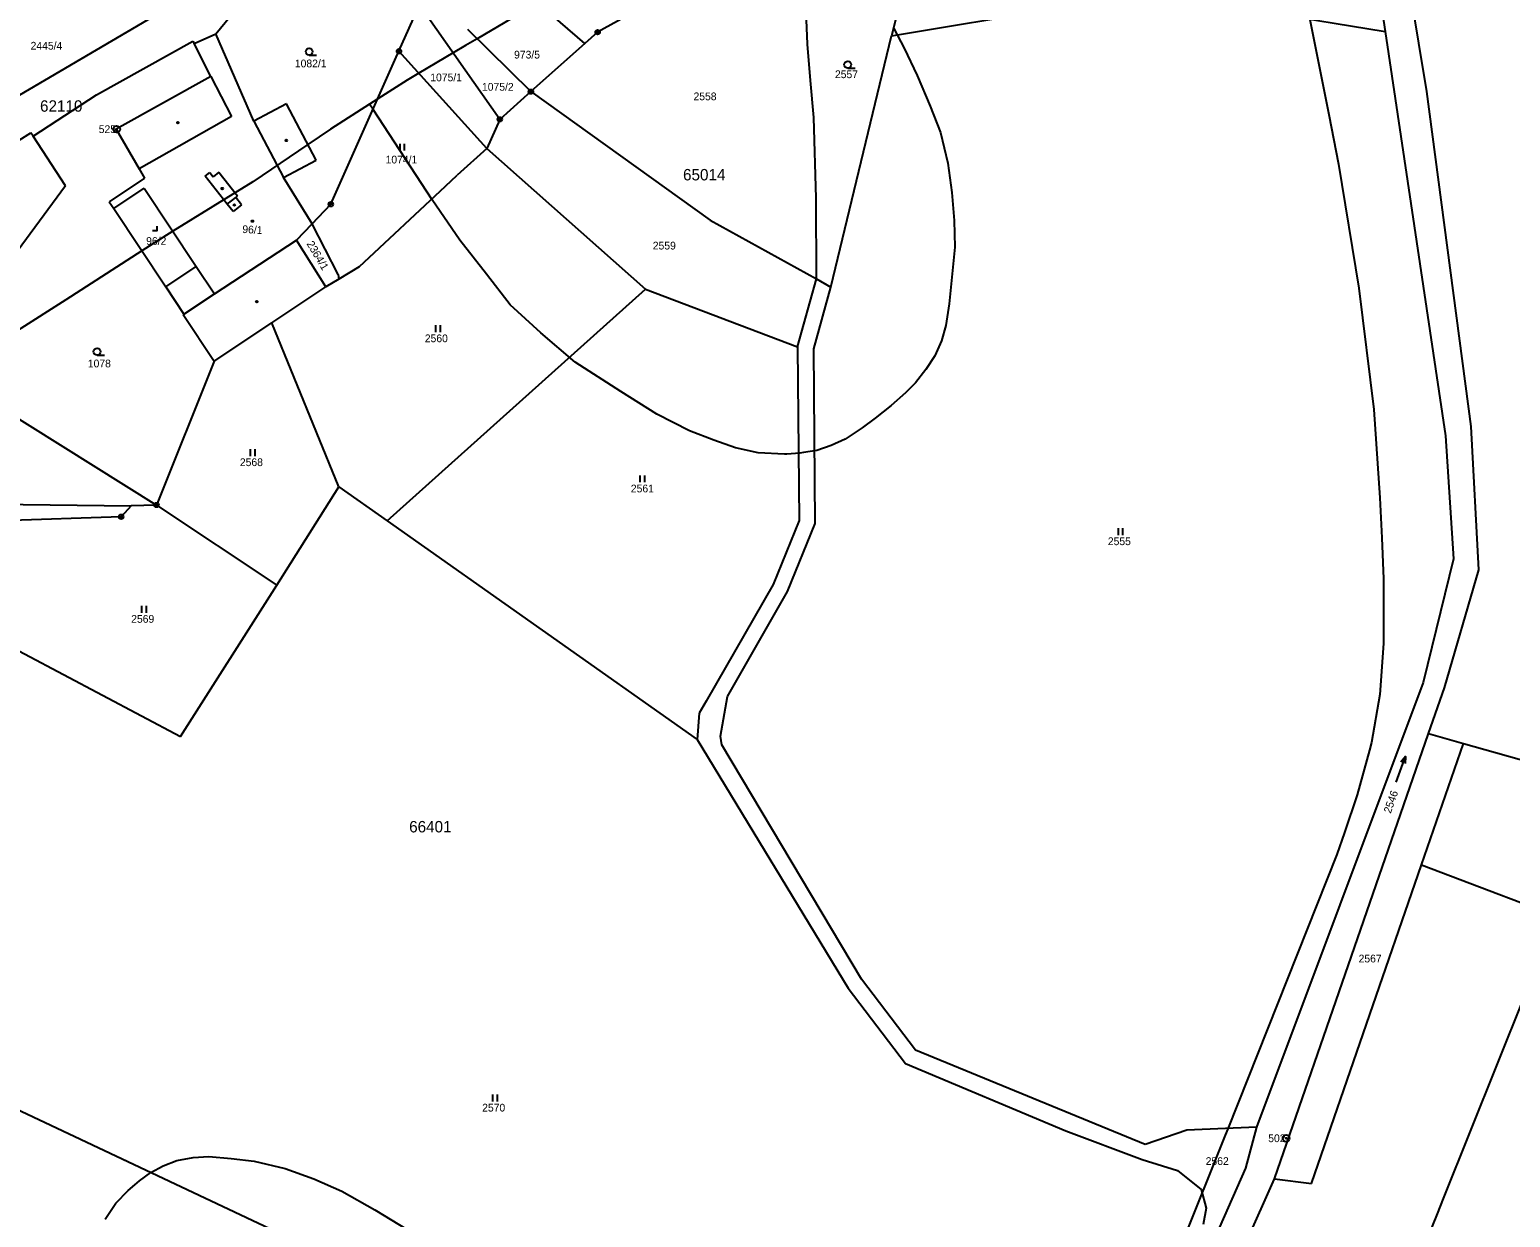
# Model space of a CAD drawing. Extents: x -546762 to -540209, y -1046851 to -1035694.
# Drawn here: x -543169.9 to -542845.1, y -1040575.9 to -1040315.5 of the extents above; entities that cross this region are included whole.
import ezdxf

# ---------------------------------------------------------------- set-up
doc = ezdxf.new("R2010")
doc.units = 0
for name, color, linetype in [('Vrstva 1', 7, 'Continuous'), ('Vrstva 17', 7, 'Continuous'), ('Vrstva 18', 7, 'Continuous'), ('Vrstva 19', 7, 'Continuous'), ('Vrstva 24', 7, 'Continuous'), ('Vrstva 25', 7, 'Continuous'), ('Vrstva 3', 7, 'Continuous'), ('Vrstva 37', 7, 'Continuous'), ('Vrstva 4', 7, 'Continuous'), ('Vrstva 52', 7, 'Continuous'), ('Vrstva 53', 7, 'Continuous')]:
    doc.layers.add(name, color=color, linetype=linetype)

msp = doc.modelspace()

# ---------------------------------------------------------------- linework, layer by layer
at = {"layer": 'Vrstva 1'}
msp.add_line((-543102.19, -1040369.21), (-543102.05, -1040370.19), dxfattribs=at)
for points in [[(-542876.59, -1040289.15), (-542872.58, -1040315.87)], [(-542974.46, -1040291.54), (-542980.8, -1040316.89)], [(-543188, -1040339.15), (-543119.06, -1040298.69)], [(-542999.24, -1040318.65), (-543000.14, -1040297.52)], [(-542863.38, -1040329.08), (-542868.75, -1040296.78)], [(-543023.91, -1040304.21), (-543045.27, -1040316.06)], [(-543048.07, -1040318.56), (-543058.79, -1040309.3)], [(-543129.03, -1040316.45), (-543125.93, -1040312.7)], [(-543088.85, -1040320.24), (-543084.34, -1040310.1)], [(-543066.73, -1040335.17), (-543084.34, -1040310.1)], [(-542980.8, -1040316.89), (-542944.78, -1040310.88)], [(-542898.51, -1040311.7), (-542872.58, -1040315.87)], [(-543073.81, -1040315.43), (-543059.9, -1040329.09)], [(-542872.58, -1040315.87), (-542859.29, -1040404.58)], [(-543155.2, -1040329.77), (-543134.03, -1040318)], [(-543134.03, -1040318), (-543133.76, -1040318.53)], [(-543133.76, -1040318.53), (-543129.03, -1040316.45)], [(-543130.09, -1040325.75), (-543133.76, -1040318.53)], [(-543120.69, -1040335.53), (-543129.03, -1040316.45)], [(-543048.07, -1040318.56), (-543059.9, -1040329.09)], [(-543045.27, -1040316.06), (-543048.07, -1040318.56)], [(-542998.62, -1040326.65), (-542999.24, -1040318.65)], [(-542994.15, -1040371.97), (-542980.8, -1040316.89)], [(-543103.78, -1040353.78), (-543088.85, -1040320.24)], [(-543069.55, -1040341.59), (-543088.85, -1040320.24)], [(-543130.09, -1040325.75), (-543150.86, -1040337.29)], [(-542997.83, -1040334.73), (-542998.62, -1040326.65)], [(-543169.09, -1040338.87), (-543155.2, -1040329.77)], [(-543113.53, -1040331.74), (-543120.69, -1040335.53)], [(-543106.98, -1040344.11), (-543113.53, -1040331.74)], [(-543059.9, -1040329.09), (-543066.73, -1040335.17)], [(-543059.9, -1040329.09), (-543020.6, -1040357.3)], [(-542853.67, -1040402.48), (-542863.38, -1040329.08)], [(-543066.73, -1040335.17), (-543069.55, -1040341.59)], [(-542997.35, -1040352.46), (-542997.83, -1040334.73)], [(-543192.68, -1040352.56), (-543169.57, -1040338.13)], [(-543169.09, -1040338.87), (-543169.57, -1040338.13)], [(-543150.86, -1040337.29), (-543145.83, -1040346)], [(-543161.98, -1040349.72), (-543169.09, -1040338.87)], [(-543069.55, -1040341.59), (-543076.05, -1040347.39)], [(-543069.55, -1040341.59), (-543034.74, -1040372.42)], [(-543114.14, -1040347.9), (-543106.98, -1040344.11)], [(-543144.63, -1040348.09), (-543152.39, -1040353.25)], [(-543145.83, -1040346), (-543144.63, -1040348.09)], [(-543107.86, -1040358.04), (-543114.14, -1040347.9)], [(-543078.67, -1040349.8), (-543076.05, -1040347.39)], [(-543161.98, -1040349.72), (-543174.41, -1040366.6)], [(-543151.42, -1040354.71), (-543144.73, -1040350.26)], [(-543144.73, -1040350.26), (-543133.29, -1040367.45)], [(-543097.58, -1040367.53), (-543078.67, -1040349.8)], [(-543152.39, -1040353.25), (-543151.42, -1040354.71)], [(-543151.42, -1040354.71), (-543139.98, -1040371.9)], [(-543107.86, -1040358.04), (-543103.78, -1040353.78)], [(-542997.29, -1040370.12), (-542997.35, -1040352.46)], [(-543111.3, -1040361.62), (-543107.86, -1040358.04)], [(-543102.19, -1040369.21), (-543107.86, -1040358.04)], [(-543020.6, -1040357.3), (-542997.29, -1040370.12)], [(-543104.91, -1040371.89), (-543111.3, -1040361.62)], [(-543133.29, -1040367.45), (-543129.3, -1040373.44)], [(-543097.58, -1040367.53), (-543102.05, -1040370.19)], [(-543102.05, -1040370.19), (-543104.91, -1040371.89)], [(-543001.4, -1040385.03), (-542997.29, -1040370.12)], [(-542997.29, -1040370.12), (-542994.15, -1040371.97)], [(-543139.98, -1040371.9), (-543136.02, -1040377.85)], [(-543136.02, -1040377.85), (-543129.3, -1040373.44)], [(-543116.72, -1040379.75), (-543104.91, -1040371.89)], [(-543091.43, -1040423.21), (-543034.74, -1040372.42)], [(-543034.74, -1040372.42), (-543001.4, -1040385.03)], [(-542997.88, -1040385.49), (-542994.15, -1040371.97)], [(-543136.02, -1040377.85), (-543136.19, -1040377.96)], [(-543136.19, -1040377.96), (-543129.37, -1040388.16)], [(-543129.37, -1040388.16), (-543116.72, -1040379.75)], [(-543102.01, -1040415.76), (-543116.72, -1040379.75)], [(-543001.4, -1040385.03), (-543001.07, -1040423.13)], [(-542997.54, -1040423.8), (-542997.88, -1040385.49)], [(-543191.01, -1040389.15), (-543142.04, -1040419.72)], [(-543129.37, -1040388.16), (-543142.04, -1040419.72)], [(-542852.01, -1040433.96), (-542853.67, -1040402.48)], [(-542859.29, -1040404.58), (-542857.54, -1040431.54)], [(-543115.66, -1040437.26), (-543102.01, -1040415.76)], [(-543102.01, -1040415.76), (-543091.43, -1040423.21)], [(-543177.24, -1040419.54), (-543147.61, -1040419.88)], [(-543147.61, -1040419.88), (-543149.78, -1040422.29)], [(-543142.04, -1040419.72), (-543147.61, -1040419.88)], [(-543142.04, -1040419.72), (-543115.66, -1040437.26)], [(-543149.78, -1040422.29), (-543176.05, -1040423.16)], [(-543001.07, -1040423.13), (-543006.77, -1040437.14)], [(-543091.43, -1040423.21), (-543023.41, -1040471.14)], [(-543003.6, -1040438.69), (-542997.54, -1040423.8)], [(-542857.54, -1040431.54), (-542864.24, -1040458.64)], [(-542859.56, -1040459.81), (-542852.01, -1040433.96)], [(-543136.77, -1040470.51), (-543115.66, -1040437.26)], [(-543006.77, -1040437.14), (-543021.45, -1040462.72)], [(-543016.79, -1040461.67), (-543003.6, -1040438.69)], [(-543179.6, -1040447.83), (-543136.77, -1040470.51)], [(-542864.24, -1040458.64), (-542900.74, -1040556.16)], [(-543018.35, -1040470.4), (-543016.79, -1040461.67)], [(-542863.03, -1040469.83), (-542859.56, -1040459.81)], [(-543022.97, -1040465.37), (-543023.41, -1040471.14)], [(-543021.45, -1040462.72), (-543022.97, -1040465.37)], [(-543023.41, -1040471.14), (-542990.3, -1040525.68)], [(-543018.01, -1040472.31), (-543018.35, -1040470.4)], [(-542896.79, -1040567.42), (-542863.03, -1040469.83)], [(-542863.03, -1040469.83), (-542855.39, -1040471.98)], [(-542987.38, -1040523.71), (-543018.01, -1040472.31)], [(-542864.59, -1040498.63), (-542855.39, -1040471.98)], [(-542855.39, -1040471.98), (-542802.33, -1040486.92)], [(-542888.69, -1040568.48), (-542864.59, -1040498.63)], [(-542864.59, -1040498.63), (-542718.05, -1040554.12)], [(-542975.52, -1040539.28), (-542987.38, -1040523.71)], [(-542990.3, -1040525.68), (-542977.75, -1040542.16)], [(-543082.01, -1040595.03), (-543215.93, -1040531.84)], [(-542925.15, -1040559.91), (-542975.52, -1040539.28)], [(-542977.75, -1040542.16), (-542942.58, -1040556.94)], [(-542900.74, -1040556.16), (-542916.01, -1040556.78)], [(-542900.74, -1040556.16), (-542903.17, -1040565.13)], [(-542942.58, -1040556.94), (-542925.87, -1040563.24)], [(-542916.01, -1040556.78), (-542925.15, -1040559.91)], [(-542903.17, -1040565.13), (-542943.67, -1040656.98)], [(-542925.87, -1040563.24), (-542918.06, -1040565.62)], [(-542918.06, -1040565.62), (-542912.89, -1040569.81)], [(-542914.9, -1040607.98), (-542896.79, -1040567.42)], [(-542896.79, -1040567.42), (-542888.69, -1040568.48)], [(-542912.89, -1040569.81), (-542911.81, -1040573.85)], [(-542911.81, -1040573.85), (-542912.45, -1040577.46)]]:
    msp.add_lwpolyline(points, dxfattribs=at)
at = {"layer": 'Vrstva 24'}
for centre, radius in [((-543045.27, -1040316.06), 0.5), ((-543045.27, -1040316.06), 0.1), ((-543088.85, -1040320.24), 0.5), ((-543088.85, -1040320.24), 0.1), ((-543059.9, -1040329.09), 0.5), ((-543059.9, -1040329.09), 0.1), ((-543066.73, -1040335.17), 0.5), ((-543066.73, -1040335.17), 0.1), ((-543150.77, -1040337.32), 0.75), ((-543150.77, -1040337.32), 0.1), ((-543103.78, -1040353.78), 0.5), ((-543103.78, -1040353.78), 0.1), ((-543142.04, -1040419.72), 0.5), ((-543142.04, -1040419.72), 0.1), ((-543149.78, -1040422.29), 0.5), ((-543149.78, -1040422.29), 0.1), ((-542894.27, -1040558.56), 0.75), ((-542894.27, -1040558.56), 0.1)]:
    msp.add_circle(centre, radius, dxfattribs=at)
at = {"layer": 'Vrstva 25'}
for p, q in [((-543108.54, -1040321.06), (-543106.94, -1040321.06)), ((-542990.42, -1040323.92), (-542988.82, -1040323.92)), ((-543088.61, -1040342.01), (-543088.61, -1040340.51)), ((-543087.61, -1040342.01), (-543087.61, -1040340.51)), ((-543080.77, -1040381.82), (-543080.77, -1040380.32)), ((-543079.77, -1040381.82), (-543079.77, -1040380.32)), ((-543155.06, -1040386.84), (-543153.46, -1040386.84)), ((-543121.39, -1040408.98), (-543121.39, -1040407.48)), ((-543120.39, -1040408.98), (-543120.39, -1040407.48)), ((-543035.92, -1040414.74), (-543035.92, -1040413.24)), ((-543034.92, -1040414.74), (-543034.92, -1040413.24)), ((-542931.06, -1040426.31), (-542931.06, -1040424.81)), ((-542930.06, -1040426.31), (-542930.06, -1040424.81)), ((-543145.22, -1040443.33), (-543145.22, -1040441.83)), ((-543144.22, -1040443.33), (-543144.22, -1040441.83)), ((-543068.23, -1040550.49), (-543068.23, -1040548.99)), ((-543067.23, -1040550.49), (-543067.23, -1040548.99))]:
    msp.add_line(p, q, dxfattribs=at)
for points in [[(-543142.9, -1040359.56), (-543141.9, -1040359.56), (-543141.9, -1040358.56)], [(-542870.15, -1040480.48), (-542868.09, -1040474.84), (-542869.08, -1040476.08)], [(-542868.09, -1040474.84), (-542868.14, -1040476.42)]]:
    msp.add_lwpolyline(points, dxfattribs=at)
for centre, radius in [((-543108.54, -1040320.31), 0.75), ((-542990.42, -1040323.17), 0.75), ((-543137.34, -1040335.9), 0.175), ((-543113.57, -1040339.79), 0.175), ((-543127.61, -1040350.34), 0.175), ((-543124.94, -1040353.94), 0.175), ((-543120.98, -1040357.49), 0.175), ((-543120.03, -1040375.15), 0.175), ((-543155.06, -1040386.09), 0.75)]:
    msp.add_circle(centre, radius, dxfattribs=at)
at = {"layer": 'Vrstva 3'}
for points in [[(-543133.76, -1040318.53), (-543129.03, -1040316.45)], [(-543130.09, -1040325.75), (-543133.76, -1040318.53)], [(-543120.69, -1040335.53), (-543129.03, -1040316.45)], [(-543130.09, -1040325.75), (-543125.61, -1040334.57)], [(-543125.61, -1040334.57), (-543145.83, -1040346)], [(-543120.69, -1040335.53), (-543114.14, -1040347.9)], [(-543144.63, -1040348.09), (-543152.39, -1040353.25)], [(-543145.83, -1040346), (-543144.63, -1040348.09)], [(-543131.35, -1040347.62), (-543130.33, -1040346.81)], [(-543126.51, -1040353.73), (-543131.35, -1040347.62)], [(-543130.33, -1040346.81), (-543129.58, -1040347.75)], [(-543128.33, -1040346.76), (-543129.58, -1040347.75)], [(-543128.33, -1040346.76), (-543124.23, -1040351.94)], [(-543107.86, -1040358.04), (-543114.14, -1040347.9)], [(-543151.42, -1040354.71), (-543144.73, -1040350.26)], [(-543144.73, -1040350.26), (-543133.29, -1040367.45)], [(-543152.39, -1040353.25), (-543151.42, -1040354.71)], [(-543125.2, -1040355.38), (-543126.51, -1040353.73)], [(-543123.36, -1040353.92), (-543125.2, -1040355.38)], [(-543124.66, -1040352.28), (-543124.23, -1040351.94)], [(-543123.36, -1040353.92), (-543124.66, -1040352.28)], [(-543111.3, -1040361.62), (-543107.86, -1040358.04)], [(-543129.3, -1040373.44), (-543111.3, -1040361.62)], [(-543133.29, -1040367.45), (-543129.3, -1040373.44)]]:
    msp.add_lwpolyline(points, dxfattribs=at)
at = {"layer": 'Vrstva 37'}
msp.add_circle((-543120.98, -1040357.49), 0.175, dxfattribs=at)
at = {"layer": 'Vrstva 4'}
for points in [[(-543130.09, -1040325.75), (-543125.61, -1040334.57)], [(-543125.61, -1040334.57), (-543145.83, -1040346)], [(-543120.69, -1040335.53), (-543114.14, -1040347.9)], [(-543131.35, -1040347.62), (-543130.33, -1040346.81)], [(-543126.51, -1040353.73), (-543131.35, -1040347.62)], [(-543130.33, -1040346.81), (-543129.58, -1040347.75)], [(-543128.33, -1040346.76), (-543129.58, -1040347.75)], [(-543128.33, -1040346.76), (-543124.23, -1040351.94)], [(-543126.51, -1040353.73), (-543124.66, -1040352.28)], [(-543125.2, -1040355.38), (-543126.51, -1040353.73)], [(-543123.36, -1040353.92), (-543125.2, -1040355.38)], [(-543124.66, -1040352.28), (-543124.23, -1040351.94)], [(-543123.36, -1040353.92), (-543124.66, -1040352.28)], [(-543129.3, -1040373.44), (-543111.3, -1040361.62)], [(-543139.98, -1040371.9), (-543133.29, -1040367.45)]]:
    msp.add_lwpolyline(points, dxfattribs=at)
at = {"layer": 'Vrstva 52'}
for points in [[(-542904.81, -1040188.55), (-542904.99, -1040195.25), (-542905.09, -1040198.97), (-542905.19, -1040201.73), (-542905.52, -1040210.92), (-542904.94, -1040226.73), (-542904.9, -1040227.7), (-542904.5, -1040231.14), (-542902.55, -1040247.83), (-542899.15, -1040266.66), (-542896.48, -1040278.22), (-542895.36, -1040283.09), (-542894.41, -1040287.21), (-542893.66, -1040290.46), (-542893.64, -1040290.56), (-542892.24, -1040297.54), (-542891.88, -1040299.34), (-542884.92, -1040334.13), (-542882.75, -1040344.99), (-542878.3, -1040372.19), (-542875, -1040398.79)], [(-543006.26, -1040277.12), (-543016.27, -1040283.52), (-543025.08, -1040289.16), (-543029.79, -1040292.08), (-543041.54, -1040299.36), (-543042.87, -1040300.17), (-543056, -1040308.16), (-543058.41, -1040309.63), (-543059.58, -1040310.34), (-543071.71, -1040317.49), (-543074.22, -1040318.97), (-543076.97, -1040320.6), (-543084.49, -1040325.06), (-543087.03, -1040326.56), (-543093.5, -1040330.69), (-543095.32, -1040331.85)], [(-542980.3, -1040315.28), (-542978.01, -1040319.55), (-542975.18, -1040325.53), (-542972.34, -1040332.25), (-542970.1, -1040338.08), (-542968.45, -1040344.8), (-542967.56, -1040351.23), (-542967.11, -1040357.36), (-542966.96, -1040363.19), (-542967.56, -1040369.76), (-542968.15, -1040375.59), (-542968.93, -1040380.35), (-542969.88, -1040383.7), (-542971.32, -1040387.01), (-542973.28, -1040390), (-542975.59, -1040392.9), (-542977.72, -1040395.12), (-542980.88, -1040397.94), (-542984.38, -1040400.67), (-542987.28, -1040402.81), (-542990.95, -1040405.28), (-542994.02, -1040406.65), (-542997.18, -1040407.76), (-543000.11, -1040408.23), (-543000.94, -1040408.36), (-543003.75, -1040408.57)], [(-543095.32, -1040331.85), (-543103.89, -1040337.33), (-543108.81, -1040340.66), (-543120.88, -1040348.83), (-543138.44, -1040359.71), (-543142.83, -1040362.43), (-543145.25, -1040363.99), (-543161.92, -1040374.73), (-543184.92, -1040389.37)], [(-543003.75, -1040408.57), (-543004.26, -1040408.61), (-543010.07, -1040408.27), (-543015.02, -1040407.16), (-543019.8, -1040405.54), (-543025.09, -1040403.49), (-543032.26, -1040399.82), (-543040.22, -1040394.8), (-543050.23, -1040388.37), (-543057.7, -1040381.95), (-543064.42, -1040375.82), (-543069.65, -1040369.1), (-543075.47, -1040361.62), (-543081.59, -1040352.81), (-543094.54, -1040333.03), (-543095.32, -1040331.85)], [(-542875, -1040398.79), (-542873.7, -1040418.14), (-542873.31, -1040426.89), (-542872.91, -1040435.93), (-542872.91, -1040450.05), (-542873.7, -1040461.3), (-542875.53, -1040471.76), (-542876, -1040473.5), (-542878.66, -1040483.27), (-542881.47, -1040491.53), (-542883.11, -1040496.34), (-542907.05, -1040556.47), (-542907.61, -1040557.89), (-542908.19, -1040559.33), (-542909.52, -1040562.62), (-542915.49, -1040577.42), (-542923.48, -1040597.25), (-542924.63, -1040600.11), (-542925.9, -1040603.26), (-542941.01, -1040640.73), (-542952.35, -1040664.73), (-542973.03, -1040708.47), (-542977.75, -1040718.65), (-542982.34, -1040726.85)], [(-542864.2, -1040582.89), (-542861.09, -1040575.12), (-542859.74, -1040571.76), (-542841.99, -1040527.48)], [(-543153.27, -1040576.33), (-543150.97, -1040572.82), (-543148.24, -1040570.01), (-543146.8, -1040568.77), (-543145.76, -1040567.87), (-543143.29, -1040566.08), (-543140.56, -1040564.63), (-543137.57, -1040563.43), (-543133.98, -1040562.75), (-543130.57, -1040562.58), (-543125.62, -1040563), (-543120.58, -1040563.6), (-543113.84, -1040565.22), (-543107.52, -1040567.44), (-543101.38, -1040570.18), (-543094.12, -1040574.28), (-543087.04, -1040578.55)]]:
    msp.add_lwpolyline(points, dxfattribs=at)

# ---------------------------------------------------------------- texts
at = {"layer": 'Vrstva 17'}
for s, p in [('525', (-543154.69, -1040338.17)), ('502', (-542898.19, -1040559.41))]:
    msp.add_text(s, height=1.7, dxfattribs=at).set_placement(p)
at = {"layer": 'Vrstva 18'}
for s, p in [('2445/4', (-543169.64, -1040319.88)), ('1082/1', (-543111.68, -1040323.76)), ('973/5', (-543063.6, -1040321.83)), ('1075/1', (-543081.98, -1040326.82)), ('2557', (-542993.22, -1040326.13)), ('1075/2', (-543070.64, -1040328.89)), ('2558', (-543024.25, -1040330.98)), ('1074/1', (-543091.78, -1040344.84)), ('2559', (-543033.18, -1040363.7)), ('2560', (-543083.18, -1040384.03)), ('1078', (-543157.09, -1040389.54)), ('2568', (-543123.74, -1040411.19)), ('2561', (-543037.99, -1040416.95)), ('2555', (-542933.37, -1040428.52)), ('2569', (-543147.58, -1040445.54)), ('2567', (-542878.37, -1040520.01)), ('2570', (-543070.6, -1040552.7)), ('2562', (-542911.91, -1040564.42))]:
    msp.add_text(s, height=1.7, dxfattribs=at).set_placement(p)
for s, rotation, p in [('2364/1', 300.6, (-543109.16, -1040362.44)), ('2546', 70.7496, (-542871.33, -1040487.46))]:
    msp.add_text(s, height=1.7, rotation=rotation, dxfattribs=at).set_placement(p)
at = {"layer": 'Vrstva 19'}
msp.add_text('96/2', height=1.7, dxfattribs=at).set_placement((-543144.29, -1040362.67))
msp.add_text('96/1', height=1.7, rotation=356.8237, dxfattribs=at).set_placement((-543123.24, -1040360.07))
at = {"layer": 'Vrstva 53'}
for s, p in [('62110', (-543167.57, -1040333.49)), ('65014', (-543026.54, -1040348.55)), ('66401', (-543086.61, -1040491.5))]:
    msp.add_text(s, height=2.5, dxfattribs=at).set_placement(p)

doc.saveas('drawing.dxf')
